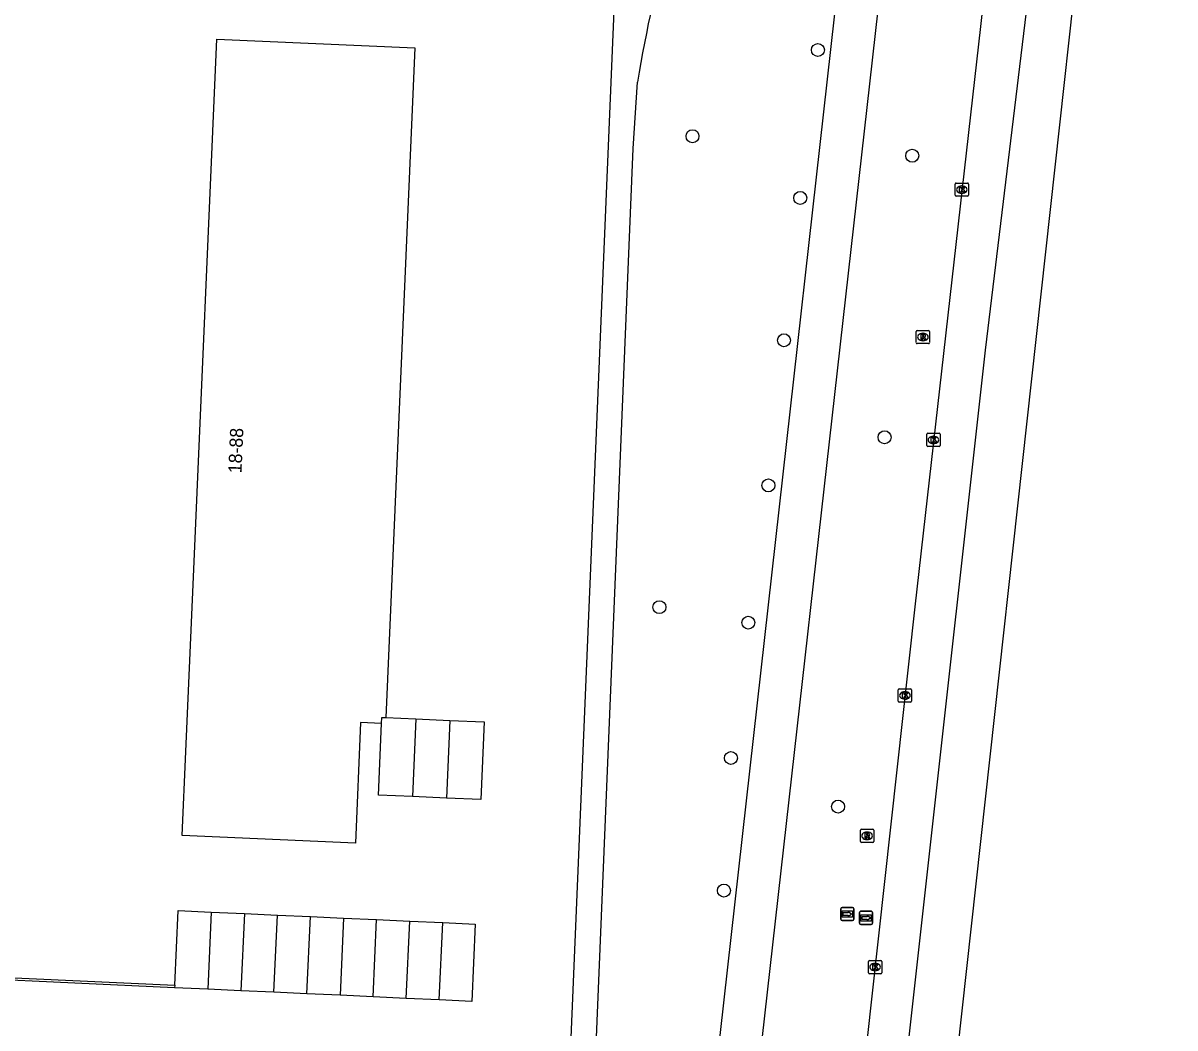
# Model space of a CAD drawing. Extents: x 161355 to 162026, y 386504 to 387459.
# Drawn here: x 161895 to 161982, y 386903.7 to 386979.6 of the extents above; entities that cross this region are included whole.
import ezdxf

# ---------------------------------------------------------------- set-up
doc = ezdxf.new("R2010")
doc.units = 0
for name, color, linetype in [('IMGEO_Boom', 7, 'Continuous'), ('IMGEO_Fietspad_gesloten', 7, 'Continuous'), ('IMGEO_Kolk', 7, 'Continuous'), ('IMGEO_Muur', 7, 'Continuous'), ('IMGEO_Pand', 7, 'Continuous'), ('IMGEO_Pand_nummerreeks', 7, 'Continuous'), ('IMGEO_Rijbaan_regionaal_gesloten', 7, 'Continuous'), ('IMGEO_Rioolput', 7, 'Continuous'), ('IMGEO_Voetpad_halfverhard', 7, 'Continuous'), ('IMGEO_Wegwijzer', 7, 'Continuous')]:
    doc.layers.add(name, color=color, linetype=linetype)

msp = doc.modelspace()

# ---------------------------------------------------------------- linework, layer by layer
at = {"layer": 'IMGEO_Boom'}
for centre in [(161955.019, 386977.518), (161945.55, 386971.009), (161962.142, 386969.533), (161953.686, 386966.346), (161952.46, 386955.604), (161960.052, 386948.28), (161951.282, 386944.646), (161943.052, 386935.456), (161949.767, 386934.285), (161948.456, 386924.068), (161956.544, 386920.397), (161947.924, 386914.063)]:
    msp.add_circle(centre, 0.489, dxfattribs=at)
at = {"layer": 'IMGEO_Fietspad_gesloten'}
for points in [[(161909.577, 386666.417), (161913.466, 386677.408), (161920.088, 386699.556), (161931.111, 386738.486), (161933.024, 386747.211), (161933.448, 386750), (161936.822, 386778.776), (161938.796, 386796.287), (161960.38, 386987.709), (161961.639, 387000), (161967.257, 387050.915)], [(161964.191, 387051.221), (161958.492, 387000), (161935.661, 386796.635), (161932.945, 386772.439), (161930.197, 386750), (161930.041, 386748.73), (161927.704, 386738.292), (161921.99, 386717.644), (161913.777, 386689.388)]]:
    msp.add_lwpolyline(points, dxfattribs=at)
at = {"layer": 'IMGEO_Kolk'}
for p, q in [((161965.388, 386966.547), (161965.388, 386967.399)), ((161965.463, 386967.473), (161966.315, 386967.473)), ((161966.389, 386967.399), (161966.389, 386966.547)), ((161966.315, 386966.473), (161965.463, 386966.473)), ((161965.899, 386966.693), (161965.874, 386966.693)), ((161965.876, 386967.253), (161965.901, 386967.253)), ((161963.246, 386947.653), (161963.246, 386948.505)), ((161963.321, 386948.579), (161964.173, 386948.579)), ((161963.734, 386948.359), (161963.759, 386948.359)), ((161964.247, 386948.505), (161964.247, 386947.653)), ((161964.173, 386947.579), (161963.321, 386947.579)), ((161963.757, 386947.799), (161963.732, 386947.799)), ((161961.094, 386928.366), (161961.094, 386929.218)), ((161961.169, 386929.292), (161962.021, 386929.292)), ((161961.582, 386929.072), (161961.607, 386929.072)), ((161962.095, 386929.218), (161962.095, 386928.366)), ((161962.021, 386928.292), (161961.169, 386928.292)), ((161961.605, 386928.512), (161961.58, 386928.512)), ((161958.836, 386907.86), (161958.836, 386908.712)), ((161958.911, 386908.786), (161959.763, 386908.786)), ((161959.324, 386908.566), (161959.349, 386908.566)), ((161959.837, 386908.712), (161959.837, 386907.86)), ((161959.763, 386907.786), (161958.911, 386907.786)), ((161959.347, 386908.006), (161959.322, 386908.006))]:
    msp.add_line(p, q, dxfattribs=at)
for points in [[(161965.388, 386966.547), (161965.388, 386967.399)], [(161965.463, 386967.473), (161966.315, 386967.473)], [(161966.389, 386967.399), (161966.389, 386966.547)], [(161966.315, 386966.473), (161965.463, 386966.473)], [(161965.709, 386967.173), (161965.832, 386967.173), (161965.832, 386967.022), (161965.962, 386967.173), (161966.126, 386967.173), (161965.98, 386967.022), (161966.133, 386966.773), (161965.981, 386966.773), (161965.896, 386966.937), (161965.832, 386966.87), (161965.832, 386966.773), (161965.709, 386966.773), (161965.709, 386967.173)], [(161963.246, 386947.653), (161963.246, 386948.505)], [(161963.321, 386948.579), (161964.173, 386948.579)], [(161963.567, 386948.279), (161963.69, 386948.279), (161963.69, 386948.128), (161963.82, 386948.279), (161963.984, 386948.279), (161963.838, 386948.128), (161963.991, 386947.879), (161963.839, 386947.879), (161963.754, 386948.043), (161963.69, 386947.976), (161963.69, 386947.879), (161963.567, 386947.879), (161963.567, 386948.279)], [(161964.247, 386948.505), (161964.247, 386947.653)], [(161964.173, 386947.579), (161963.321, 386947.579)], [(161961.094, 386928.366), (161961.094, 386929.218)], [(161961.169, 386929.292), (161962.021, 386929.292)], [(161962.095, 386929.218), (161962.095, 386928.366)], [(161962.021, 386928.292), (161961.169, 386928.292)], [(161961.415, 386928.992), (161961.538, 386928.992), (161961.538, 386928.841), (161961.668, 386928.992), (161961.832, 386928.992), (161961.686, 386928.841), (161961.839, 386928.592), (161961.687, 386928.592), (161961.602, 386928.756), (161961.538, 386928.689), (161961.538, 386928.592), (161961.415, 386928.592), (161961.415, 386928.992)], [(161958.836, 386907.86), (161958.836, 386908.712)], [(161958.911, 386908.786), (161959.763, 386908.786)], [(161959.157, 386908.486), (161959.28, 386908.486), (161959.28, 386908.335), (161959.41, 386908.486), (161959.574, 386908.486), (161959.428, 386908.335), (161959.581, 386908.086), (161959.429, 386908.086), (161959.344, 386908.25), (161959.28, 386908.183), (161959.28, 386908.086), (161959.157, 386908.086), (161959.157, 386908.486)], [(161959.837, 386908.712), (161959.837, 386907.86)], [(161959.763, 386907.786), (161958.911, 386907.786)]]:
    msp.add_lwpolyline(points, dxfattribs=at)
for centre, start, end in [((161965.465, 386967.397), 91.55205, 178.44795), ((161965.465, 386967.397), 91.55205, 178.44795), ((161966.313, 386967.397), 1.55205, 88.44795), ((161966.313, 386967.397), 1.55205, 88.44795), ((161965.465, 386966.549), 181.55205, 268.44795), ((161965.465, 386966.549), 181.55205, 268.44795), ((161966.313, 386966.549), 271.55205, 358.44795), ((161966.313, 386966.549), 271.55205, 358.44795), ((161963.323, 386948.503), 91.55205, 178.44795), ((161963.323, 386948.503), 91.55205, 178.44795), ((161964.171, 386948.503), 1.55205, 88.44795), ((161964.171, 386948.503), 1.55205, 88.44795), ((161963.323, 386947.655), 181.55205, 268.44795), ((161963.323, 386947.655), 181.55205, 268.44795), ((161964.171, 386947.655), 271.55205, 358.44795), ((161964.171, 386947.655), 271.55205, 358.44795), ((161961.171, 386929.216), 91.55205, 178.44795), ((161961.171, 386929.216), 91.55205, 178.44795), ((161962.019, 386929.216), 1.55205, 88.44795), ((161962.019, 386929.216), 1.55205, 88.44795), ((161961.171, 386928.368), 181.55205, 268.44795), ((161961.171, 386928.368), 181.55205, 268.44795), ((161962.019, 386928.368), 271.55205, 358.44795), ((161962.019, 386928.368), 271.55205, 358.44795), ((161958.913, 386908.71), 91.55205, 178.44795), ((161958.913, 386908.71), 91.55205, 178.44795), ((161959.761, 386908.71), 1.55205, 88.44795), ((161959.761, 386908.71), 1.55205, 88.44795), ((161958.913, 386907.862), 181.55205, 268.44795), ((161958.913, 386907.862), 181.55205, 268.44795), ((161959.761, 386907.862), 271.55205, 358.44795), ((161959.761, 386907.862), 271.55205, 358.44795)]:
    msp.add_arc(centre, 0.0765, start, end, dxfattribs=at)
for centre, major_axis, ratio, start_param, end_param in [((161965.875, 386966.973), (-0.387, 0.002), 0.722429, 4.712389, 7.853982), ((161965.9, 386966.973), (-0.39, 0.002), 0.717154, 1.570796, 4.712389), ((161963.733, 386948.079), (-0.387, 0.002), 0.722429, 4.712389, 7.853982), ((161963.758, 386948.079), (-0.39, 0.002), 0.717154, 1.570796, 4.712389), ((161961.581, 386928.792), (-0.387, 0.002), 0.722429, 4.712389, 7.853982), ((161961.606, 386928.792), (-0.39, 0.002), 0.717154, 1.570796, 4.712389), ((161959.323, 386908.286), (-0.387, 0.002), 0.722429, 4.712389, 7.853982), ((161959.348, 386908.286), (-0.39, 0.002), 0.717154, 1.570796, 4.712389)]:
    msp.add_ellipse(centre, major_axis=major_axis, ratio=ratio, start_param=start_param, end_param=end_param, dxfattribs=at)
at = {"layer": 'IMGEO_Muur'}
for points in [[(161892.138, 386925.204), (161892.338, 386925.195), (161891.578, 386907.611), (161906.455, 386906.926)], [(161906.446, 386906.726), (161891.37, 386907.42), (161891.965, 386921.204)]]:
    msp.add_lwpolyline(points, dxfattribs=at)
at = {"layer": 'IMGEO_Pand'}
for points in [[(161922.067, 386926.675), (161920.488, 386926.744), (161920.093, 386917.65), (161907.022, 386918.218), (161907.298, 386924.565), (161907.845, 386937.154), (161909.635, 386978.326), (161924.585, 386977.677), (161922.388, 386927.113)], [(161924.407, 386921.152), (161921.832, 386921.264), (161922.067, 386926.675)], [(161922.067, 386926.675), (161922.085, 386927.13), (161922.388, 386927.113)], [(161922.388, 386927.113), (161924.662, 386927.014)], [(161924.662, 386927.014), (161924.407, 386921.152)], [(161924.662, 386927.014), (161927.238, 386926.902)], [(161927.238, 386926.902), (161929.812, 386926.79), (161929.558, 386920.928), (161926.983, 386921.04)], [(161927.238, 386926.902), (161926.983, 386921.04)], [(161926.983, 386921.04), (161924.407, 386921.152)], [(161906.455, 386906.926), (161906.714, 386912.556), (161909.211, 386912.441)], [(161909.211, 386912.441), (161908.943, 386906.611)], [(161909.211, 386912.441), (161911.709, 386912.326)], [(161911.709, 386912.326), (161911.441, 386906.496)], [(161911.709, 386912.326), (161914.206, 386912.211)], [(161913.938, 386906.382), (161914.206, 386912.211)], [(161914.206, 386912.211), (161916.703, 386912.097)], [(161916.435, 386906.267), (161916.703, 386912.097)], [(161916.703, 386912.097), (161919.201, 386911.982)], [(161919.201, 386911.982), (161918.933, 386906.152)], [(161919.201, 386911.982), (161921.698, 386911.867)], [(161921.43, 386906.037), (161921.698, 386911.867)], [(161921.698, 386911.867), (161924.196, 386911.752)], [(161923.928, 386905.922), (161924.196, 386911.752)], [(161924.196, 386911.752), (161926.693, 386911.638)], [(161926.693, 386911.638), (161929.146, 386911.525), (161928.878, 386905.694), (161926.425, 386905.807)], [(161926.425, 386905.807), (161926.693, 386911.638)], [(161906.455, 386906.926), (161906.446, 386906.726)], [(161908.943, 386906.611), (161906.446, 386906.726)], [(161911.441, 386906.496), (161908.943, 386906.611)], [(161913.938, 386906.382), (161911.441, 386906.496)], [(161916.435, 386906.267), (161913.938, 386906.382)], [(161918.933, 386906.152), (161916.435, 386906.267)], [(161921.43, 386906.037), (161918.933, 386906.152)], [(161923.928, 386905.922), (161921.43, 386906.037)], [(161926.425, 386905.807), (161923.928, 386905.922)]]:
    msp.add_lwpolyline(points, dxfattribs=at)
at = {"layer": 'IMGEO_Rijbaan_regionaal_gesloten'}
for points in [[(161975.237, 387050.12), (161969.651, 387000), (161962.329, 386935.471), (161954.584, 386865.29), (161949.337, 386819.995), (161945.681, 386796.648), (161945.484, 386795.546)], [(161981.984, 387049.448), (161976.049, 386997.238), (161962.379, 386873.244), (161953.318, 386794.679), (161940.783, 386677.087), (161933.982, 386612.625), (161933.498, 386609.431), (161932.687, 386601.55), (161929.934, 386573.912), (161926.119, 386532.024)], [(161978.469, 387049.798), (161974.354, 387011.236), (161973.137, 387000.209), (161967.661, 386954.866), (161949.872, 386795.06)]]:
    msp.add_lwpolyline(points, dxfattribs=at)
at = {"layer": 'IMGEO_Rioolput'}
for p, q in [((161962.449, 386955.422), (161962.449, 386956.274)), ((161962.524, 386956.348), (161963.376, 386956.348)), ((161962.937, 386956.128), (161962.962, 386956.128)), ((161963.45, 386956.274), (161963.45, 386955.422)), ((161963.376, 386955.348), (161962.524, 386955.348)), ((161962.96, 386955.568), (161962.935, 386955.568)), ((161958.235, 386917.767), (161958.235, 386918.619)), ((161958.31, 386918.693), (161959.162, 386918.693)), ((161959.236, 386918.619), (161959.236, 386917.767)), ((161958.746, 386917.913), (161958.721, 386917.913)), ((161958.723, 386918.473), (161958.748, 386918.473)), ((161959.162, 386917.693), (161958.31, 386917.693))]:
    msp.add_line(p, q, dxfattribs=at)
for points in [[(161962.449, 386955.422), (161962.449, 386956.274)], [(161962.524, 386956.348), (161963.376, 386956.348)], [(161963.038, 386956.046), (161962.786, 386956.048), (161962.786, 386955.648)], [(161963.45, 386956.274), (161963.45, 386955.422)], [(161963.376, 386955.348), (161962.524, 386955.348)], [(161962.786, 386955.648), (161962.91, 386955.648), (161962.91, 386955.81), (161962.921, 386955.81)], [(161962.964, 386955.967), (161962.91, 386955.967), (161962.91, 386955.886)], [(161962.91, 386955.886), (161962.962, 386955.886)], [(161962.968, 386955.781), (161963.039, 386955.648), (161963.179, 386955.648), (161963.114, 386955.774)], [(161958.235, 386917.767), (161958.235, 386918.619)], [(161958.31, 386918.693), (161959.162, 386918.693)], [(161959.236, 386918.619), (161959.236, 386917.767)], [(161958.824, 386918.391), (161958.572, 386918.393), (161958.572, 386917.993)], [(161958.572, 386917.993), (161958.696, 386917.993), (161958.696, 386918.155), (161958.707, 386918.155)], [(161958.75, 386918.312), (161958.696, 386918.312), (161958.696, 386918.231)], [(161958.696, 386918.231), (161958.748, 386918.231)], [(161958.754, 386918.126), (161958.825, 386917.993), (161958.965, 386917.993), (161958.9, 386918.119)], [(161959.162, 386917.693), (161958.31, 386917.693)]]:
    msp.add_lwpolyline(points, dxfattribs=at)
for centre, radius, start, end in [((161962.526, 386956.272), 0.0765, 91.55205, 178.44795), ((161962.526, 386956.272), 0.0765, 91.55205, 178.44795), ((161963.037, 386955.936), 0.109, 350.36119, 89.41601), ((161963.374, 386956.272), 0.0765, 1.55205, 88.44795), ((161963.374, 386956.272), 0.0765, 1.55205, 88.44795), ((161962.526, 386955.424), 0.0765, 181.55205, 268.44795), ((161962.526, 386955.424), 0.0765, 181.55205, 268.44795), ((161962.92, 386955.757), 0.0533, 26.02933, 88.69889), ((161962.946, 386956.075), 0.19, 274.7715, 282.96867), ((161962.97, 386955.871), 0.0964, 77.00612, 93.18647), ((161962.984, 386955.928), 0.0378, 276.66336, 79.67722), ((161963.035, 386955.936), 0.112, 277.58423, 350.98172), ((161963.019, 386955.721), 0.108, 29.51342, 73.79051), ((161963.374, 386955.424), 0.0765, 271.55205, 358.44795), ((161963.374, 386955.424), 0.0765, 271.55205, 358.44795), ((161958.312, 386918.617), 0.0765, 91.55205, 178.44795), ((161958.312, 386918.617), 0.0765, 91.55205, 178.44795), ((161959.16, 386918.617), 0.0765, 1.55205, 88.44795), ((161959.16, 386918.617), 0.0765, 1.55205, 88.44795), ((161958.312, 386917.769), 0.0765, 181.55205, 268.44795), ((161958.312, 386917.769), 0.0765, 181.55205, 268.44795), ((161958.706, 386918.102), 0.0533, 26.02933, 88.69889), ((161958.732, 386918.42), 0.19, 274.7715, 282.96867), ((161958.756, 386918.216), 0.0964, 77.00612, 93.18647), ((161958.77, 386918.273), 0.0378, 276.66336, 79.67722), ((161958.823, 386918.281), 0.109, 350.36119, 89.41601), ((161958.821, 386918.281), 0.112, 277.58423, 350.98172), ((161958.805, 386918.066), 0.108, 29.51342, 73.79051), ((161959.16, 386917.769), 0.0765, 271.55205, 358.44795), ((161959.16, 386917.769), 0.0765, 271.55205, 358.44795)]:
    msp.add_arc(centre, radius, start, end, dxfattribs=at)
for centre, major_axis, ratio, start_param, end_param in [((161962.936, 386955.848), (-0.387, 0.002), 0.722429, 4.712389, 7.853982), ((161962.961, 386955.848), (-0.39, 0.002), 0.717154, 1.570796, 4.712389), ((161958.722, 386918.193), (-0.387, 0.002), 0.722429, 4.712389, 7.853982), ((161958.747, 386918.193), (-0.39, 0.002), 0.717154, 1.570796, 4.712389)]:
    msp.add_ellipse(centre, major_axis=major_axis, ratio=ratio, start_param=start_param, end_param=end_param, dxfattribs=at)
at = {"layer": 'IMGEO_Voetpad_halfverhard'}
for points in [[(161936.238, 386899.338), (161940.02, 386989.533)], [(161937.723, 386895.33), (161938.146, 386899.309), (161941.082, 386970.072), (161941.407, 386975.097)]]:
    msp.add_lwpolyline(points, dxfattribs=at)
msp.add_arc((162043.236, 386958.619), 103.153, 157.58635, 170.80783, dxfattribs=at)
at = {"layer": 'IMGEO_Wegwijzer'}
for p, q in [((161956.742, 386911.89), (161956.742, 386912.69)), ((161956.742, 386912.69), (161956.742, 386911.89)), ((161956.842, 386912.79), (161957.632, 386912.79)), ((161957.632, 386912.79), (161956.842, 386912.79)), ((161957.732, 386912.69), (161957.732, 386911.89)), ((161957.732, 386911.89), (161957.732, 386912.69)), ((161957.632, 386911.79), (161956.842, 386911.79)), ((161956.842, 386911.79), (161957.632, 386911.79)), ((161958.161, 386911.595), (161958.161, 386912.395)), ((161958.161, 386912.395), (161958.161, 386911.595)), ((161958.261, 386912.495), (161959.051, 386912.495)), ((161959.051, 386912.495), (161958.261, 386912.495)), ((161959.151, 386912.395), (161959.151, 386911.595)), ((161959.151, 386911.595), (161959.151, 386912.395)), ((161959.051, 386911.495), (161958.261, 386911.495)), ((161958.261, 386911.495), (161959.051, 386911.495))]:
    msp.add_line(p, q, dxfattribs=at)
for points in [[(161956.843, 386912.522), (161957.631, 386912.522), (161957.631, 386912.058), (161956.843, 386912.058), (161956.843, 386912.522)], [(161956.908, 386912.374), (161956.908, 386912.29), (161956.908, 386912.206), (161957.319, 386912.206), (161957.319, 386912.123), (161957.566, 386912.29), (161957.319, 386912.457), (161957.319, 386912.374), (161956.908, 386912.374)], [(161958.262, 386912.227), (161959.05, 386912.227), (161959.05, 386911.763), (161958.262, 386911.763), (161958.262, 386912.227)], [(161958.327, 386912.079), (161958.327, 386911.995), (161958.327, 386911.911), (161958.738, 386911.911), (161958.738, 386911.828), (161958.985, 386911.995), (161958.738, 386912.162), (161958.738, 386912.079), (161958.327, 386912.079)]]:
    msp.add_lwpolyline(points, dxfattribs=at)
for centre, start, end in [((161956.842, 386912.69), 90, 180), ((161956.842, 386912.69), 90, 180), ((161957.632, 386912.69), 0, 90), ((161957.632, 386912.69), 360, 90), ((161956.842, 386911.89), 180, 270), ((161956.842, 386911.89), 180, 270), ((161957.632, 386911.89), 270, 0), ((161957.632, 386911.89), 270, 0), ((161958.261, 386912.395), 90, 180), ((161958.261, 386912.395), 90, 180), ((161959.051, 386912.395), 0, 90), ((161959.051, 386912.395), 360, 90), ((161958.261, 386911.595), 180, 270), ((161958.261, 386911.595), 180, 270), ((161959.051, 386911.595), 270, 0), ((161959.051, 386911.595), 270, 0)]:
    msp.add_arc(centre, 0.1, start, end, dxfattribs=at)

# ---------------------------------------------------------------- texts
at = {"layer": 'IMGEO_Pand_nummerreeks'}
msp.add_text('18-88', height=1, rotation=87.51082, dxfattribs=at).set_placement((161911.493, 386945.55))

doc.saveas('drawing.dxf')
